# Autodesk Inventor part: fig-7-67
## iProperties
Shininess: 64.0
Length Units: 11269
Angle Units: 11279
Time Units: 11290
Mass Units: 11283
Length Display Precision: 3
Angle Display Precision: 2
Compacted: True
Part Number: fig-7-67
Document SubType Name: Modeling
Created: 2002-12
Designer: deepak
Density: 0.0
Volumn: 0.0
Area: 0.0
PropertySet Name: Model Information
Control State: 0
Master: False
Checked Out: False
Author: deepak
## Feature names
1. Extrusion1
